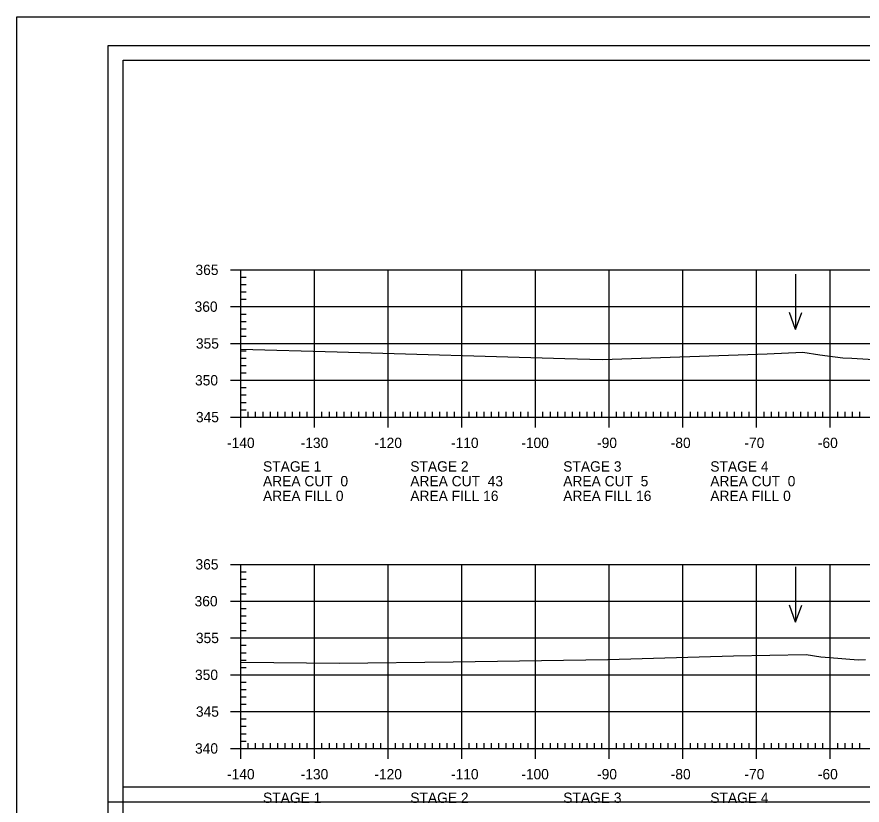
# Model space of a CAD drawing. Extents: x 1368910 to 1369601, y 380116 to 380950.
# Drawn here: x 1369267.2 to 1369381.9, y 380630.1 to 380737.1 of the extents above; entities that cross this region are included whole.
import ezdxf

# ---------------------------------------------------------------- set-up
doc = ezdxf.new("R2010")
doc.units = 0
for name, color, linetype in [('R_Axis', 7, 'Continuous'), ('R_Axis Annot', 7, 'Continuous'), ('R_Border', 7, 'Continuous'), ('R_Border Plan-Plan', 7, 'Continuous'), ('R_Exist Surface', 7, 'Continuous'), ('R_Grid', 7, 'Continuous'), ('R_No Plot', 7, 'Continuous'), ('R_Water Annot', 7, 'Continuous')]:
    doc.layers.add(name, color=color, linetype=linetype)

msp = doc.modelspace()

# ---------------------------------------------------------------- linework, layer by layer
at = {"layer": 'R_Axis'}
for p, q in [((1369296.19, 380702.76), (1369298.99, 380702.76)), ((1369297.59, 380682.76), (1369297.59, 380702.76)), ((1369297.59, 380701.76), (1369298.29, 380701.76)), ((1369297.59, 380700.76), (1369298.29, 380700.76)), ((1369297.59, 380699.76), (1369298.29, 380699.76)), ((1369297.59, 380698.76), (1369298.29, 380698.76)), ((1369296.19, 380697.76), (1369298.99, 380697.76)), ((1369297.59, 380696.76), (1369298.29, 380696.76)), ((1369297.59, 380695.76), (1369298.29, 380695.76)), ((1369297.59, 380694.76), (1369298.29, 380694.76)), ((1369297.59, 380693.76), (1369298.29, 380693.76)), ((1369296.19, 380692.76), (1369298.99, 380692.76)), ((1369297.59, 380691.76), (1369298.29, 380691.76)), ((1369297.59, 380690.76), (1369298.29, 380690.76)), ((1369297.59, 380689.76), (1369298.29, 380689.76)), ((1369297.59, 380688.76), (1369298.29, 380688.76)), ((1369296.19, 380687.76), (1369298.99, 380687.76)), ((1369297.59, 380686.76), (1369298.29, 380686.76)), ((1369297.59, 380685.76), (1369298.29, 380685.76)), ((1369297.59, 380684.76), (1369298.29, 380684.76)), ((1369297.59, 380681.36), (1369297.59, 380684.16)), ((1369297.59, 380683.76), (1369298.29, 380683.76)), ((1369298.59, 380682.76), (1369298.59, 380683.46)), ((1369299.59, 380682.76), (1369299.59, 380683.46)), ((1369300.59, 380682.76), (1369300.59, 380683.46)), ((1369301.59, 380682.76), (1369301.59, 380683.46)), ((1369302.59, 380682.76), (1369302.59, 380683.46)), ((1369303.59, 380682.76), (1369303.59, 380683.46)), ((1369304.59, 380682.76), (1369304.59, 380683.46)), ((1369305.59, 380682.76), (1369305.59, 380683.46)), ((1369306.59, 380682.76), (1369306.59, 380683.46)), ((1369307.59, 380681.36), (1369307.59, 380684.16)), ((1369308.59, 380682.76), (1369308.59, 380683.46)), ((1369309.59, 380682.76), (1369309.59, 380683.46)), ((1369310.59, 380682.76), (1369310.59, 380683.46)), ((1369311.59, 380682.76), (1369311.59, 380683.46)), ((1369312.59, 380682.76), (1369312.59, 380683.46)), ((1369313.59, 380682.76), (1369313.59, 380683.46)), ((1369314.59, 380682.76), (1369314.59, 380683.46)), ((1369315.59, 380682.76), (1369315.59, 380683.46)), ((1369316.59, 380682.76), (1369316.59, 380683.46)), ((1369317.59, 380681.36), (1369317.59, 380684.16)), ((1369318.59, 380682.76), (1369318.59, 380683.46)), ((1369319.59, 380682.76), (1369319.59, 380683.46)), ((1369320.59, 380682.76), (1369320.59, 380683.46)), ((1369321.59, 380682.76), (1369321.59, 380683.46)), ((1369322.59, 380682.76), (1369322.59, 380683.46)), ((1369323.59, 380682.76), (1369323.59, 380683.46)), ((1369324.59, 380682.76), (1369324.59, 380683.46)), ((1369325.59, 380682.76), (1369325.59, 380683.46)), ((1369326.59, 380682.76), (1369326.59, 380683.46)), ((1369327.59, 380681.36), (1369327.59, 380684.16)), ((1369328.59, 380682.76), (1369328.59, 380683.46)), ((1369329.59, 380682.76), (1369329.59, 380683.46)), ((1369330.59, 380682.76), (1369330.59, 380683.46)), ((1369331.59, 380682.76), (1369331.59, 380683.46)), ((1369332.59, 380682.76), (1369332.59, 380683.46)), ((1369333.59, 380682.76), (1369333.59, 380683.46)), ((1369334.59, 380682.76), (1369334.59, 380683.46)), ((1369335.59, 380682.76), (1369335.59, 380683.46)), ((1369336.59, 380682.76), (1369336.59, 380683.46)), ((1369337.59, 380681.36), (1369337.59, 380684.16)), ((1369338.59, 380682.76), (1369338.59, 380683.46)), ((1369339.59, 380682.76), (1369339.59, 380683.46)), ((1369340.59, 380682.76), (1369340.59, 380683.46)), ((1369341.59, 380682.76), (1369341.59, 380683.46)), ((1369342.59, 380682.76), (1369342.59, 380683.46)), ((1369343.59, 380682.76), (1369343.59, 380683.46)), ((1369344.59, 380682.76), (1369344.59, 380683.46)), ((1369345.59, 380682.76), (1369345.59, 380683.46)), ((1369346.59, 380682.76), (1369346.59, 380683.46)), ((1369347.59, 380681.36), (1369347.59, 380684.16)), ((1369348.59, 380682.76), (1369348.59, 380683.46)), ((1369349.59, 380682.76), (1369349.59, 380683.46)), ((1369350.59, 380682.76), (1369350.59, 380683.46)), ((1369351.59, 380682.76), (1369351.59, 380683.46)), ((1369352.59, 380682.76), (1369352.59, 380683.46)), ((1369353.59, 380682.76), (1369353.59, 380683.46)), ((1369354.59, 380682.76), (1369354.59, 380683.46)), ((1369355.59, 380682.76), (1369355.59, 380683.46)), ((1369356.59, 380682.76), (1369356.59, 380683.46)), ((1369357.59, 380681.36), (1369357.59, 380684.16)), ((1369358.59, 380682.76), (1369358.59, 380683.46)), ((1369359.59, 380682.76), (1369359.59, 380683.46)), ((1369360.59, 380682.76), (1369360.59, 380683.46)), ((1369361.59, 380682.76), (1369361.59, 380683.46)), ((1369362.59, 380682.76), (1369362.59, 380683.46)), ((1369363.59, 380682.76), (1369363.59, 380683.46)), ((1369364.59, 380682.76), (1369364.59, 380683.46)), ((1369365.59, 380682.76), (1369365.59, 380683.46)), ((1369366.59, 380682.76), (1369366.59, 380683.46)), ((1369367.59, 380681.36), (1369367.59, 380684.16)), ((1369368.59, 380682.76), (1369368.59, 380683.46)), ((1369369.59, 380682.76), (1369369.59, 380683.46)), ((1369370.59, 380682.76), (1369370.59, 380683.46)), ((1369371.59, 380682.76), (1369371.59, 380683.46)), ((1369372.59, 380682.76), (1369372.59, 380683.46)), ((1369373.59, 380682.76), (1369373.59, 380683.46)), ((1369374.59, 380682.76), (1369374.59, 380683.46)), ((1369375.59, 380682.76), (1369375.59, 380683.46)), ((1369376.59, 380682.76), (1369376.59, 380683.46)), ((1369377.59, 380681.36), (1369377.59, 380684.16)), ((1369378.59, 380682.76), (1369378.59, 380683.46)), ((1369379.59, 380682.76), (1369379.59, 380683.46)), ((1369380.59, 380682.76), (1369380.59, 380683.46)), ((1369381.59, 380682.76), (1369381.59, 380683.46)), ((1369296.19, 380682.76), (1369298.99, 380682.76)), ((1369297.59, 380682.76), (1369577.59, 380682.76)), ((1369296.19, 380662.76), (1369298.99, 380662.76)), ((1369297.59, 380637.76), (1369297.59, 380662.76)), ((1369297.59, 380661.76), (1369298.29, 380661.76)), ((1369297.59, 380660.76), (1369298.29, 380660.76)), ((1369297.59, 380659.76), (1369298.29, 380659.76)), ((1369297.59, 380658.76), (1369298.29, 380658.76)), ((1369296.19, 380657.76), (1369298.99, 380657.76)), ((1369297.59, 380656.76), (1369298.29, 380656.76)), ((1369297.59, 380655.76), (1369298.29, 380655.76)), ((1369297.59, 380654.76), (1369298.29, 380654.76)), ((1369297.59, 380653.76), (1369298.29, 380653.76)), ((1369296.19, 380652.76), (1369298.99, 380652.76)), ((1369297.59, 380651.76), (1369298.29, 380651.76)), ((1369297.59, 380650.76), (1369298.29, 380650.76)), ((1369297.59, 380649.76), (1369298.29, 380649.76)), ((1369296.19, 380647.76), (1369298.99, 380647.76)), ((1369297.59, 380648.76), (1369298.29, 380648.76)), ((1369297.59, 380646.76), (1369298.29, 380646.76)), ((1369297.59, 380645.76), (1369298.29, 380645.76)), ((1369297.59, 380644.76), (1369298.29, 380644.76)), ((1369297.59, 380643.76), (1369298.29, 380643.76)), ((1369296.19, 380642.76), (1369298.99, 380642.76)), ((1369297.59, 380641.76), (1369298.29, 380641.76)), ((1369297.59, 380640.76), (1369298.29, 380640.76)), ((1369297.59, 380639.76), (1369298.29, 380639.76)), ((1369297.59, 380636.36), (1369297.59, 380639.16)), ((1369297.59, 380638.76), (1369298.29, 380638.76)), ((1369307.59, 380636.36), (1369307.59, 380639.16)), ((1369317.59, 380636.36), (1369317.59, 380639.16)), ((1369327.59, 380636.36), (1369327.59, 380639.16)), ((1369337.59, 380636.36), (1369337.59, 380639.16)), ((1369347.59, 380636.36), (1369347.59, 380639.16)), ((1369357.59, 380636.36), (1369357.59, 380639.16)), ((1369367.59, 380636.36), (1369367.59, 380639.16)), ((1369377.59, 380636.36), (1369377.59, 380639.16)), ((1369296.19, 380637.76), (1369298.99, 380637.76)), ((1369297.59, 380637.76), (1369577.59, 380637.76)), ((1369298.59, 380637.76), (1369298.59, 380638.46)), ((1369299.59, 380637.76), (1369299.59, 380638.46)), ((1369300.59, 380637.76), (1369300.59, 380638.46)), ((1369301.59, 380637.76), (1369301.59, 380638.46)), ((1369302.59, 380637.76), (1369302.59, 380638.46)), ((1369303.59, 380637.76), (1369303.59, 380638.46)), ((1369304.59, 380637.76), (1369304.59, 380638.46)), ((1369305.59, 380637.76), (1369305.59, 380638.46)), ((1369306.59, 380637.76), (1369306.59, 380638.46)), ((1369308.59, 380637.76), (1369308.59, 380638.46)), ((1369309.59, 380637.76), (1369309.59, 380638.46)), ((1369310.59, 380637.76), (1369310.59, 380638.46)), ((1369311.59, 380637.76), (1369311.59, 380638.46)), ((1369312.59, 380637.76), (1369312.59, 380638.46)), ((1369313.59, 380637.76), (1369313.59, 380638.46)), ((1369314.59, 380637.76), (1369314.59, 380638.46)), ((1369315.59, 380637.76), (1369315.59, 380638.46)), ((1369316.59, 380637.76), (1369316.59, 380638.46)), ((1369318.59, 380637.76), (1369318.59, 380638.46)), ((1369319.59, 380637.76), (1369319.59, 380638.46)), ((1369320.59, 380637.76), (1369320.59, 380638.46)), ((1369321.59, 380637.76), (1369321.59, 380638.46)), ((1369322.59, 380637.76), (1369322.59, 380638.46)), ((1369323.59, 380637.76), (1369323.59, 380638.46)), ((1369324.59, 380637.76), (1369324.59, 380638.46)), ((1369325.59, 380637.76), (1369325.59, 380638.46)), ((1369326.59, 380637.76), (1369326.59, 380638.46)), ((1369328.59, 380637.76), (1369328.59, 380638.46)), ((1369329.59, 380637.76), (1369329.59, 380638.46)), ((1369330.59, 380637.76), (1369330.59, 380638.46)), ((1369331.59, 380637.76), (1369331.59, 380638.46)), ((1369332.59, 380637.76), (1369332.59, 380638.46)), ((1369333.59, 380637.76), (1369333.59, 380638.46)), ((1369334.59, 380637.76), (1369334.59, 380638.46)), ((1369335.59, 380637.76), (1369335.59, 380638.46)), ((1369336.59, 380637.76), (1369336.59, 380638.46)), ((1369338.59, 380637.76), (1369338.59, 380638.46)), ((1369339.59, 380637.76), (1369339.59, 380638.46)), ((1369340.59, 380637.76), (1369340.59, 380638.46)), ((1369341.59, 380637.76), (1369341.59, 380638.46)), ((1369342.59, 380637.76), (1369342.59, 380638.46)), ((1369343.59, 380637.76), (1369343.59, 380638.46)), ((1369344.59, 380637.76), (1369344.59, 380638.46)), ((1369345.59, 380637.76), (1369345.59, 380638.46)), ((1369346.59, 380637.76), (1369346.59, 380638.46)), ((1369348.59, 380637.76), (1369348.59, 380638.46)), ((1369349.59, 380637.76), (1369349.59, 380638.46)), ((1369350.59, 380637.76), (1369350.59, 380638.46)), ((1369351.59, 380637.76), (1369351.59, 380638.46)), ((1369352.59, 380637.76), (1369352.59, 380638.46)), ((1369353.59, 380637.76), (1369353.59, 380638.46)), ((1369354.59, 380637.76), (1369354.59, 380638.46)), ((1369355.59, 380637.76), (1369355.59, 380638.46)), ((1369356.59, 380637.76), (1369356.59, 380638.46)), ((1369358.59, 380637.76), (1369358.59, 380638.46)), ((1369359.59, 380637.76), (1369359.59, 380638.46)), ((1369360.59, 380637.76), (1369360.59, 380638.46)), ((1369361.59, 380637.76), (1369361.59, 380638.46)), ((1369362.59, 380637.76), (1369362.59, 380638.46)), ((1369363.59, 380637.76), (1369363.59, 380638.46)), ((1369364.59, 380637.76), (1369364.59, 380638.46)), ((1369365.59, 380637.76), (1369365.59, 380638.46)), ((1369366.59, 380637.76), (1369366.59, 380638.46)), ((1369368.59, 380637.76), (1369368.59, 380638.46)), ((1369369.59, 380637.76), (1369369.59, 380638.46)), ((1369370.59, 380637.76), (1369370.59, 380638.46)), ((1369371.59, 380637.76), (1369371.59, 380638.46)), ((1369372.59, 380637.76), (1369372.59, 380638.46)), ((1369373.59, 380637.76), (1369373.59, 380638.46)), ((1369374.59, 380637.76), (1369374.59, 380638.46)), ((1369375.59, 380637.76), (1369375.59, 380638.46)), ((1369376.59, 380637.76), (1369376.59, 380638.46)), ((1369378.59, 380637.76), (1369378.59, 380638.46)), ((1369379.59, 380637.76), (1369379.59, 380638.46)), ((1369380.59, 380637.76), (1369380.59, 380638.46)), ((1369381.59, 380637.76), (1369381.59, 380638.46))]:
    msp.add_line(p, q, dxfattribs=at)
at = {"layer": 'R_Border'}
for p, q in [((1369279.59, 380733.22), (1369595.77, 380733.22)), ((1369279.59, 380527.76), (1369279.59, 380733.22))]:
    msp.add_line(p, q, dxfattribs=at)
at = {"layer": 'R_Border Plan-Plan'}
msp.add_line((1369279.59, 380630.49), (1369595.77, 380630.49), dxfattribs=at)
at = {"layer": 'R_Exist Surface'}
for points in [[(1369297.59, 380691.99), (1369310.65, 380691.64), (1369341.57, 380690.7), (1369346.69, 380690.56), (1369369.03, 380691.36), (1369373.86, 380691.58), (1369376.18, 380691.2), (1369379.31, 380690.79), (1369380.52, 380690.74), (1369384.96, 380690.5)], [(1369297.59, 380649.48), (1369310.95, 380649.35), (1369326.38, 380649.51), (1369347.39, 380649.82), (1369364.46, 380650.32), (1369374.32, 380650.53), (1369376.32, 380650.18), (1369377.49, 380650.11), (1369381.39, 380649.8), (1369382.36, 380649.82)]]:
    msp.add_lwpolyline(points, dxfattribs=at)
at = {"layer": 'R_Grid'}
for p, q in [((1369297.59, 380702.76), (1369577.59, 380702.76)), ((1369297.59, 380682.76), (1369297.59, 380702.76)), ((1369307.59, 380682.76), (1369307.59, 380702.76)), ((1369317.59, 380682.76), (1369317.59, 380702.76)), ((1369327.59, 380682.76), (1369327.59, 380702.76)), ((1369337.59, 380682.76), (1369337.59, 380702.76)), ((1369347.59, 380682.76), (1369347.59, 380702.76)), ((1369357.59, 380682.76), (1369357.59, 380702.76)), ((1369367.59, 380682.76), (1369367.59, 380702.76)), ((1369377.59, 380682.76), (1369377.59, 380702.76)), ((1369297.59, 380697.76), (1369577.59, 380697.76)), ((1369297.59, 380692.76), (1369577.59, 380692.76)), ((1369297.59, 380687.76), (1369577.59, 380687.76)), ((1369297.59, 380682.76), (1369577.59, 380682.76)), ((1369297.59, 380662.76), (1369577.59, 380662.76)), ((1369297.59, 380637.76), (1369297.59, 380662.76)), ((1369307.59, 380637.76), (1369307.59, 380662.76)), ((1369317.59, 380637.76), (1369317.59, 380662.76)), ((1369327.59, 380637.76), (1369327.59, 380662.76)), ((1369337.59, 380637.76), (1369337.59, 380662.76)), ((1369347.59, 380637.76), (1369347.59, 380662.76)), ((1369357.59, 380637.76), (1369357.59, 380662.76)), ((1369367.59, 380637.76), (1369367.59, 380662.76)), ((1369377.59, 380637.76), (1369377.59, 380662.76)), ((1369297.59, 380657.76), (1369577.59, 380657.76)), ((1369297.59, 380652.76), (1369577.59, 380652.76)), ((1369297.59, 380647.76), (1369577.59, 380647.76)), ((1369297.59, 380642.76), (1369577.59, 380642.76)), ((1369297.59, 380637.76), (1369577.59, 380637.76))]:
    msp.add_line(p, q, dxfattribs=at)
at = {"layer": 'R_No Plot'}
for points in [[(1369267.18, 380737.11), (1369600.52, 380737.11), (1369600.52, 380523.78), (1369267.18, 380523.78)], [(1369593.77, 380632.49), (1369281.59, 380632.49), (1369281.59, 380731.22), (1369531.13, 380731.22), (1369531.13, 380721.34), (1369548.67, 380721.34), (1369572.77, 380721.34), (1369572.77, 380699.01), (1369593.77, 380699.01)], [(1369281.59, 380731.22), (1369531.13, 380731.22), (1369531.13, 380721.34), (1369548.67, 380721.34), (1369572.77, 380721.34), (1369572.77, 380699.01), (1369593.77, 380699.01), (1369593.77, 380529.76), (1369281.59, 380529.76)]]:
    msp.add_lwpolyline(points, close=True, dxfattribs=at)
at = {"layer": 'R_Water Annot'}
for p, q in [((1369372.87, 380702.18), (1369372.87, 380694.64)), ((1369372.87, 380694.64), (1369372.03, 380696.95)), ((1369372.87, 380694.64), (1369373.71, 380696.95)), ((1369372.87, 380662.44), (1369372.87, 380654.9)), ((1369372.87, 380654.9), (1369372.03, 380657.21)), ((1369372.87, 380654.9), (1369373.71, 380657.21))]:
    msp.add_line(p, q, dxfattribs=at)

# ---------------------------------------------------------------- texts
at = {"layer": 'R_Axis Annot'}
for s, p in [('365', (1369291.42, 380702.06)), ('360', (1369291.3, 380697.06)), ('355', (1369291.48, 380692.06)), ('350', (1369291.36, 380687.06)), ('345', (1369291.48, 380682.06)), ('-140', (1369295.7, 380678.56)), ('-130', (1369305.7, 380678.56)), ('-120', (1369315.7, 380678.56)), ('-110', (1369326.1, 380678.56)), ('-100', (1369335.64, 380678.56)), ('-90', (1369345.93, 380678.56)), ('-80', (1369355.93, 380678.56)), ('-70', (1369365.93, 380678.56)), ('-60', (1369375.9, 380678.56)), ('STAGE 1', (1369300.59, 380675.36)), ('STAGE 2', (1369320.58, 380675.36)), ('STAGE 3', (1369341.34, 380675.36)), ('STAGE 4', (1369361.3, 380675.36)), ('AREA CUT  0', (1369300.59, 380673.36)), ('AREA CUT  43', (1369320.58, 380673.36)), ('AREA CUT  5', (1369341.34, 380673.36)), ('AREA CUT  0', (1369361.3, 380673.36)), ('AREA FILL 0', (1369300.59, 380671.36)), ('AREA FILL 16', (1369320.58, 380671.36)), ('AREA FILL 16', (1369341.34, 380671.36)), ('AREA FILL 0', (1369361.3, 380671.36)), ('365', (1369291.42, 380662.06)), ('360', (1369291.3, 380657.06)), ('355', (1369291.48, 380652.06)), ('350', (1369291.36, 380647.06)), ('345', (1369291.48, 380642.06)), ('340', (1369291.36, 380637.06)), ('-140', (1369295.7, 380633.56)), ('-130', (1369305.7, 380633.56)), ('-120', (1369315.7, 380633.56)), ('-110', (1369326.1, 380633.56)), ('-100', (1369335.64, 380633.56)), ('-90', (1369345.93, 380633.56)), ('-80', (1369355.93, 380633.56)), ('-70', (1369365.93, 380633.56)), ('-60', (1369375.9, 380633.56)), ('STAGE 1', (1369300.59, 380630.36)), ('STAGE 2', (1369320.58, 380630.36)), ('STAGE 3', (1369341.34, 380630.36)), ('STAGE 4', (1369361.3, 380630.36))]:
    msp.add_text(s, height=1.4, dxfattribs=at).set_placement(p)

doc.saveas('drawing.dxf')
